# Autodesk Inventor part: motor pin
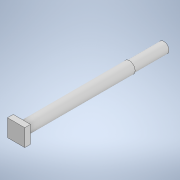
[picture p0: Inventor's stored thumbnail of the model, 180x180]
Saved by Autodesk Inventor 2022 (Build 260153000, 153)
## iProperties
Created: 2021-07
Part Number: motor pin
Material: Generic
Document SubType Name: Modeling
Designer: 91876
Density: 1 g/cm^3
Appearance: Default
Author: 91876
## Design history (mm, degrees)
sketch "Sketch1"
  geometry: C1 r 10 at (0, 0); 1 further point
  constraints: 1 centre point, 1 coincident
  dimensions: "d0" = 20 diameter of C1
extrude "Extrusion1" new body sketch "Sketch1" distance "d1" = 192; taper "d2" = 0 deg
sketch "Sketch2"
  geometry: C1 r 9 at (0, 0); 1 further point
  constraints: 1 centre point, 1 coincident
  dimensions: "d3" = 18 diameter of C1
extrude "Extrusion2" join sketch "Sketch2" distance "d4" = 60; taper "d5" = 0 deg
sketch "Sketch3"
  geometry: L1 (15, -15)-(-15, -15); L2 (-15, -15)-(-15, 15); L3 (-15, 15)-(15, 15); L4 (15, 15)-(15, -15); L5 (15, -15)-(-15, 15); L6 (-15, -15)-(15, 15); 1 further point
  constraints: 12 end point, 2 midpoint, 2 parallel, 1 horizontal, 1 perpendicular
  dimensions: "d6" = 30 distance of L2.end L3.end; "d7" = 30 distance of L1.end L2.end
extrude "Extrusion3" join sketch "Sketch3" stored distance "d8" = 10; taper "d9" = 0 deg
body "Solid1"
